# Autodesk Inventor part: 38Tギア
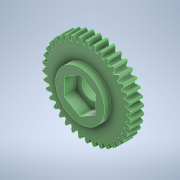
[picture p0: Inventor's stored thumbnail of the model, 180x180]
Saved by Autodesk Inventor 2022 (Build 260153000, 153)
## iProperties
CustomPartVersion: 1
Created: 2024-10
Part Number: 38Tギア
Material: アセタール樹脂、白
Document SubType Name: Modeling
Designer: shimizu
Categories: <?xml version="1.0" encoding="UTF-16"?> <MemberInstance><Categories><FamilyTemplate><FamilyTemplateParameter ValueType="xs:double" Id="1" ObjectReferenceKey="da
Density: 1.425 g/cm^3
Appearance: 滑らか - 白
Author: shimizu
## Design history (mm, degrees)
sketch "Sketch1"
  geometry: C1 r 10 at (0, 0)
  constraints: 1 centre point
  dimensions: "d0" = 20 diameter of C1 (= da_da)
extrude "Extrusion1" new body sketch "Sketch1" distance "d1" = 3 (= da_b); taper "d2" = 0 deg
workplane "Work Plane2"
sketch "Sketch2"
  geometry: C1 r 10 at (0, 0) reference; C2 r 9.5 at (0, 0)
  constraints: 1 centre point, 1 coincident
  dimensions: "d3" = 19 diameter of C2 (= da_d)
feature "ピッチ円直径" sketch "Sketch2" dims "d4" = 10, "d5" = 0
workplane "Work Plane8"
workplane "Work Plane9"
feature "平歯車" dims "da_b" = 3, "da_d" = 19, "da_aw" = 23.75, "da_da" = 20, "da_df" = 17.75, "da_dw" = 19, angle "da_beta" = 0 deg, "da_lefttooth" = 0, "da_righttooth" = 0
sketch "スケッチ3"
  geometry: C1 r 5.5 at (0, 0); 1 further point
  constraints: 1 centre point, 1 coincident
  dimensions: "d49" = 11 diameter of C1
extrude "押し出し2" join sketch "スケッチ3" distance "d50" = 1.5; taper "d51" = 0 deg
sketch "スケッチ4"
  geometry: C1 r 2 at (0, 0); 1 further point
  constraints: 1 centre point, 1 coincident
  dimensions: "d52" = 4 diameter of C1
extrude "押し出し3" cut sketch "スケッチ4" extent not by distance; stored distance "d53" = 0; taper "d54" = 0 deg
sketch "スケッチ5"
  geometry: L1 (0, -4.041)-(-3.5, -2.021); L2 (-3.5, -2.021)-(-3.5, 2.021); L3 (-3.5, 2.021)-(0, 4.041); L4 (0, 4.041)-(3.5, 2.021); L5 (3.5, 2.021)-(3.5, -2.021); L6 (3.5, -2.021)-(0, -4.041); 2 further points
  constraints: 12 end point, 1 coincident, 1 vertical alignment, 13 other
  dimensions: "d55" = 7 distance between parallel lines of L5 L2
extrude "押し出し4" cut sketch "スケッチ5" distance "d56" = 2.5; taper "d57" = 0 deg
body "Solid1"
body "Srf1"
other parameters: "d16" = 23.75 (= da_aw), "d17" = 0, "d34" = 0.82673 (computed from da_z), "d39" = 0, "d41" = 0, "d43" = 23.75 (= da_aw), "d46" = 23.75 (= da_aw), "d47" = 0, "d48" = 0
